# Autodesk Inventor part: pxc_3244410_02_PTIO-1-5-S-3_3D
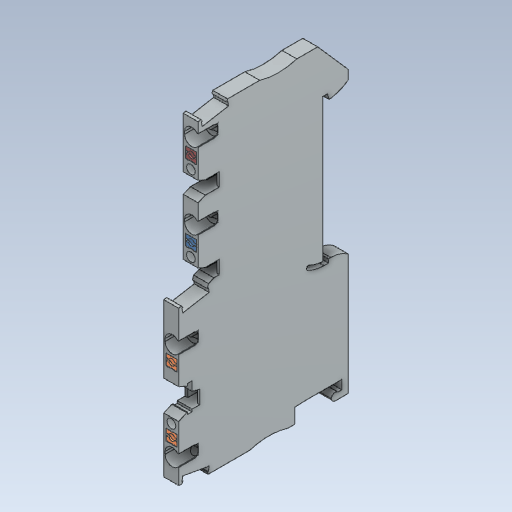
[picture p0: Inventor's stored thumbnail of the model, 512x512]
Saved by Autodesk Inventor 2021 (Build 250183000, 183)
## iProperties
Created: 2017-10
Part Number: pxc_3244410_02_PTIO-1-5-S-3_3D
Material: Genérico
Description: Creo Elements/Direct Modeling STEP Export
Document SubType Name: Modeling
Designer: ATOUZA
Density: 1 g/cm^3
Appearance: Valor por defecto
Title: D:/temp/JobSpoolerServerData/JobServer Files/4fedac82-1c3b-4573-94b3-79ddd4890bc4/work/output/model.stp
Sending System: Creo Elements/Direct Modeling 18.1I  14-Aug-2016 (C) Parametric Technology GmbH
Preprocessor: Creo Elements/Direct Modeling STEP processor for AP214 (Solid Model)
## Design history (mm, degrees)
feature "PTIO_1.5_S_3-select_1:1"
node "Sólido1"
